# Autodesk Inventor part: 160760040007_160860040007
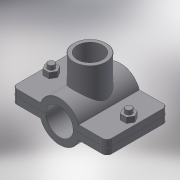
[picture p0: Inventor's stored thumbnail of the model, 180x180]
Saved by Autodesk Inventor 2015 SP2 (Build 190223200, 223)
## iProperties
Created: 2017-05
Part Number: 160760040007_160860040007
Material: Generic
Description: PLASSON SADDLE 40-3/4"
Document SubType Name: Modeling
Designer: KIM
Density: 1 g/cm^3
Appearance: Default
Author: KIM
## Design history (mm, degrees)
derived "16076.ipt"
feature "Solid1::16076.ipt"
feature "Solid2::16076.ipt"
tag "TaggingFeature1"
body "Solid1"
other parameters: "d0" = 56, "d1" = 92, "d5" = 0, "d6" = 4.6, "d7" = 92, "d8" = 0.1, "d10" = 0, "d11" = 0.4, "d14" = 31.3521, "d20" = 0.4, "d23" = 0.4, "d37" = 8, "d38" = 28, "d39" = 0, "d40" = 3, "d41" = 5, "d42" = 0, "d43" = 6, "d44" = 3, "d45" = 0, "d46" = 0.4, "d51" = 46, "d52" = 24.117, "d53" = 19, "d54" = 0, "d55" = 19, "d57" = 0, "d58" = 43.2, "d60" = 0, "d66" = 0, "B_" = 19, "G_" = 24.117, "A_" = 46, "L_" = 92, "l_2" = 19
